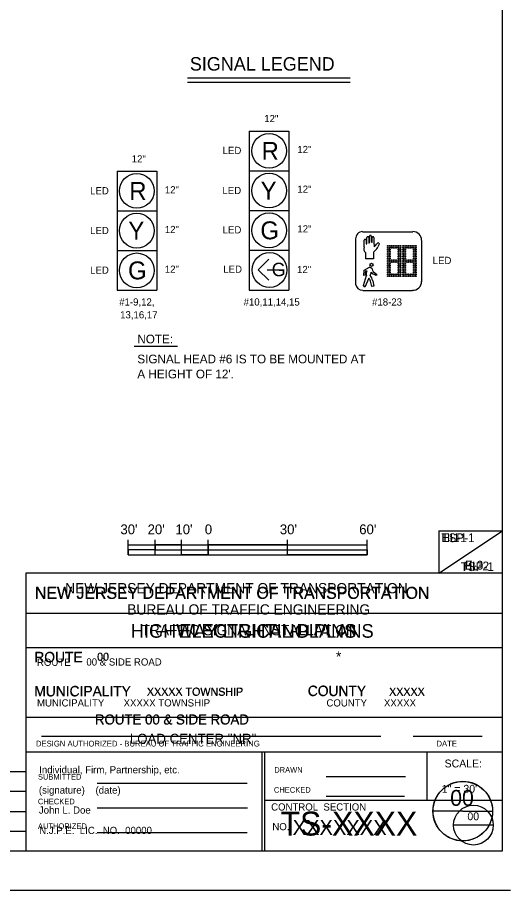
# Model space of a CAD drawing. Extents: x 488740 to 507913, y 466518 to 497949.
# Drawn here: x 507910.118 to 507910.636, y 496046.406 to 496047.323 of the extents above; entities that cross this region are included whole.
import ezdxf

# ---------------------------------------------------------------- set-up
doc = ezdxf.new("R2010")
doc.units = 0
for name, color, linetype in [('1', 7, 'Continuous'), ('11', 7, 'Continuous'), ('25', 7, 'Continuous'), ('26', 7, 'Continuous'), ('27', 7, 'Continuous'), ('31', 7, 'Continuous'), ('38', 7, 'Continuous'), ('9', 7, 'Continuous')]:
    doc.layers.add(name, color=color, linetype=linetype)

msp = doc.modelspace()

# ---------------------------------------------------------------- linework, layer by layer
at = {"layer": '1'}
for p, q in [((507910.6273, 496046.44783), (507910.6273, 496048.19783)), ((507910.6273, 496046.44783), (507910.6273, 496046.80647)), ((507910.23454, 496046.75859), (507910.23454, 496046.77434)), ((507910.26276, 496046.75859), (507910.26276, 496046.77434)), ((507910.29032, 496046.75859), (507910.29032, 496046.77434)), ((507910.31853, 496046.75859), (507910.31853, 496046.77434)), ((507910.40186, 496046.75859), (507910.40186, 496046.77434)), ((507910.4852, 496046.75859), (507910.4852, 496046.77434)), ((507910.23454, 496046.76909), (507910.4852, 496046.76909)), ((507910.23454, 496046.75859), (507910.4852, 496046.75859)), ((507907.8773, 496046.44783), (507910.6273, 496046.44783)), ((507910.63583, 496046.40617), (507907.72408, 496046.40617))]:
    msp.add_line(p, q, dxfattribs=at)
for points in [[(507910.23454, 496046.76351), (507910.2352, 496046.76384)], [(507910.26276, 496046.75859), (507910.26276, 496046.75859)]]:
    msp.add_lwpolyline(points, dxfattribs=at)
for points in [[(507910.23454, 496046.75859), (507910.26276, 496046.75859), (507910.26276, 496046.76384), (507910.23454, 496046.76384)], [(507910.26276, 496046.76384), (507910.29032, 496046.76384), (507910.29032, 496046.76909), (507910.26276, 496046.76909)], [(507910.29032, 496046.76384), (507910.31853, 496046.76384), (507910.31853, 496046.75859), (507910.29032, 496046.75859)], [(507910.31853, 496046.76384), (507910.40186, 496046.76384), (507910.40186, 496046.76909), (507910.31853, 496046.76909)], [(507910.40186, 496046.76384), (507910.4852, 496046.76384), (507910.4852, 496046.75859), (507910.40186, 496046.75859)]]:
    msp.add_lwpolyline(points, close=True, dxfattribs=at)
at = {"layer": '25'}
for p, q in [((507910.5607, 496046.7395), (507910.6273, 496046.78379)), ((507910.5607, 496046.78379), (507910.6273, 496046.78379)), ((507910.5607, 496046.78379), (507910.5607, 496046.7395)), ((507910.1273, 496046.44783), (507910.1273, 496046.7395)), ((507910.6273, 496046.7395), (507910.1273, 496046.7395)), ((507910.1273, 496046.69751), (507910.6273, 496046.69751)), ((507910.6273, 496046.55151), (507910.1273, 496046.55151)), ((507910.37467, 496046.55151), (507910.37467, 496046.44783)), ((507910.58563, 496046.4895), (507910.55479, 496046.4895)), ((507910.58563, 496046.4895), (507910.6168, 496046.4895))]:
    msp.add_line(p, q, dxfattribs=at)
msp.add_circle((507910.58579, 496046.48959), 0.03125, dxfattribs=at)
at = {"layer": '26'}
for p, q in [((507910.5607, 496046.78379), (507910.6273, 496046.78379)), ((507910.5607, 496046.78379), (507910.5607, 496046.7395)), ((507910.5607, 496046.7395), (507910.6273, 496046.78379)), ((507910.1273, 496046.44783), (507910.1273, 496046.7395)), ((507910.6273, 496046.7395), (507910.1273, 496046.7395)), ((507910.1273, 496046.69751), (507910.6273, 496046.69751)), ((507910.58563, 496046.4895), (507910.55479, 496046.4895)), ((507910.58563, 496046.4895), (507910.6168, 496046.4895))]:
    msp.add_line(p, q, dxfattribs=at)
msp.add_circle((507910.58564, 496046.48943), 0.03125, dxfattribs=at)
at = {"layer": '27'}
for p, q in [((507910.5607, 496046.78379), (507910.6273, 496046.78379)), ((507910.5607, 496046.78379), (507910.5607, 496046.7395)), ((507910.5607, 496046.7395), (507910.6273, 496046.78379)), ((507910.6271, 496046.73938), (507910.1271, 496046.73938)), ((507910.1273, 496046.44783), (507910.1273, 496046.7395)), ((507910.6271, 496046.66096), (507910.1271, 496046.66096)), ((507910.6271, 496046.5878), (507910.1271, 496046.5878)), ((507910.14337, 496046.56824), (507910.49967, 496046.56824)), ((507910.53346, 496046.56824), (507910.60597, 496046.56824)), ((507910.6271, 496046.55138), (507910.1271, 496046.55138)), ((507910.37795, 496046.44783), (507910.37795, 496046.55151)), ((507910.54823, 496046.50098), (507910.54823, 496046.55151)), ((507909.68861, 496046.53117), (507910.1273, 496046.53117)), ((507910.44247, 496046.52575), (507910.52559, 496046.52575)), ((507910.2021, 496046.51903), (507910.35925, 496046.51903)), ((507910.2021, 496046.51903), (507910.35925, 496046.51903)), ((507909.68861, 496046.5105), (507910.1273, 496046.5105)), ((507910.44247, 496046.50509), (507910.52461, 496046.50509)), ((507910.6271, 496046.50086), (507910.37776, 496046.50086)), ((507909.68861, 496046.48917), (507910.1273, 496046.48917)), ((507910.2021, 496046.49311), (507910.35958, 496046.49311)), ((507910.2021, 496046.49311), (507910.35958, 496046.49311)), ((507909.68861, 496046.4685), (507910.1273, 496046.4685)), ((507910.2021, 496046.46719), (507910.35925, 496046.46719)), ((507910.57601, 496046.47507), (507910.61778, 496046.47507))]:
    msp.add_line(p, q, dxfattribs=at)
msp.add_circle((507910.59687, 496046.47484), 0.02087, dxfattribs=at)
at = {"layer": '31'}
for p, q in [((507910.29682, 496047.25947), (507910.46751, 496047.25947)), ((507910.29689, 496047.25492), (507910.46751, 496047.25492)), ((507910.36155, 496047.20341), (507910.36155, 496047.07841)), ((507910.36155, 496047.20341), (507910.40322, 496047.20341)), ((507910.40322, 496047.20341), (507910.40322, 496047.12008)), ((507910.22277, 496047.16142), (507910.22277, 496047.03642)), ((507910.22277, 496047.16142), (507910.26444, 496047.16142)), ((507910.26444, 496047.16142), (507910.26444, 496047.07808)), ((507910.36155, 496047.16175), (507910.40322, 496047.16175)), ((507910.22277, 496047.11975), (507910.26444, 496047.11975)), ((507910.36155, 496047.12008), (507910.40322, 496047.12008)), ((507910.40322, 496047.12008), (507910.40322, 496047.12008)), ((507910.40322, 496047.12008), (507910.40322, 496047.07841)), ((507910.4731, 496047.09022), (507910.4731, 496047.04265)), ((507910.48031, 496047.09777), (507910.53314, 496047.09777)), ((507910.48503, 496047.08558), (507910.48503, 496047.09187)), ((507910.48694, 496047.09187), (507910.48694, 496047.08642)), ((507910.4878, 496047.08642), (507910.4878, 496047.09326)), ((507910.4897, 496047.09326), (507910.4897, 496047.08712)), ((507910.49056, 496047.08712), (507910.49056, 496047.09187)), ((507910.49247, 496047.09187), (507910.49247, 496047.08558)), ((507910.48227, 496047.08209), (507910.48227, 496047.08897)), ((507910.48418, 496047.08897), (507910.48418, 496047.08558)), ((507910.54232, 496047.08858), (507910.54232, 496047.04528)), ((507910.22277, 496047.07808), (507910.26444, 496047.07808)), ((507910.26444, 496047.07808), (507910.26444, 496047.07808)), ((507910.26444, 496047.07808), (507910.26444, 496047.03642)), ((507910.36155, 496047.07841), (507910.36155, 496047.03642)), ((507910.36155, 496047.07841), (507910.40322, 496047.07841)), ((507910.36155, 496047.07841), (507910.40322, 496047.07841)), ((507910.40322, 496047.07841), (507910.40322, 496047.03642)), ((507910.48377, 496047.06949), (507910.48377, 496047.07579)), ((507910.4919, 496047.07605), (507910.4919, 496047.06949)), ((507910.37106, 496047.05774), (507910.38222, 496047.0689)), ((507910.4919, 496047.06949), (507910.48377, 496047.06949)), ((507910.37106, 496047.05774), (507910.38222, 496047.04692)), ((507910.38025, 496047.05774), (507910.39567, 496047.05774)), ((507910.48197, 496047.05197), (507910.48222, 496047.05765)), ((507910.48222, 496047.05765), (507910.48772, 496047.06054)), ((507910.49486, 496047.05195), (507910.49119, 496047.05379)), ((507910.49168, 496047.05601), (507910.4956, 496047.05293)), ((507910.48161, 496047.04147), (507910.48457, 496047.05188)), ((507910.48313, 496047.05236), (507910.48197, 496047.05197)), ((507910.48693, 496047.04899), (507910.483, 496047.03981)), ((507910.49035, 496047.04033), (507910.48877, 496047.04611)), ((507910.49113, 496047.04637), (507910.49245, 496047.04086)), ((507910.4956, 496047.05293), (507910.49486, 496047.05195)), ((507910.22277, 496047.03642), (507910.26444, 496047.03642)), ((507910.36155, 496047.03642), (507910.40322, 496047.03642)), ((507910.48064, 496047.03609), (507910.53281, 496047.03609)), ((507910.483, 496047.03981), (507910.48161, 496047.04147)), ((507910.49245, 496047.04086), (507910.49035, 496047.04033)), ((507910.24081, 496046.97769), (507910.28642, 496046.97769))]:
    msp.add_line(p, q, dxfattribs=at)
for centre, radius in [((507910.38245, 496047.18279), 0.01826), ((507910.24355, 496047.14074), 0.01826), ((507910.38245, 496047.14105), 0.01826), ((507910.38245, 496047.09932), 0.01826), ((507910.24355, 496047.09901), 0.01826), ((507910.50717, 496047.08292), 0.000466), ((507910.50717, 496047.08106), 0.000466), ((507910.50903, 496047.08292), 0.000466), ((507910.50903, 496047.08106), 0.000466), ((507910.5109, 496047.08292), 0.000466), ((507910.5109, 496047.08106), 0.000466), ((507910.51276, 496047.08292), 0.000466), ((507910.51276, 496047.08106), 0.000466), ((507910.51463, 496047.08292), 0.000466), ((507910.51463, 496047.08106), 0.000466), ((507910.51649, 496047.08292), 0.000466), ((507910.51649, 496047.08106), 0.000466), ((507910.51836, 496047.08292), 0.000466), ((507910.51836, 496047.08106), 0.000466), ((507910.52022, 496047.08292), 0.000466), ((507910.52022, 496047.08106), 0.000466), ((507910.52322, 496047.08292), 0.000466), ((507910.52322, 496047.08106), 0.000466), ((507910.52508, 496047.08292), 0.000466), ((507910.52508, 496047.08106), 0.000466), ((507910.52695, 496047.08292), 0.000466), ((507910.52695, 496047.08106), 0.000466), ((507910.52881, 496047.08292), 0.000466), ((507910.52881, 496047.08106), 0.000466), ((507910.53067, 496047.08292), 0.000466), ((507910.53067, 496047.08106), 0.000466), ((507910.53254, 496047.08292), 0.000466), ((507910.53254, 496047.08106), 0.000466), ((507910.5344, 496047.08292), 0.000466), ((507910.5344, 496047.08106), 0.000466), ((507910.53627, 496047.08292), 0.000466), ((507910.53627, 496047.08106), 0.000466), ((507910.24355, 496047.05728), 0.01826), ((507910.38288, 496047.05768), 0.01826), ((507910.50717, 496047.07919), 0.000466), ((507910.50717, 496047.07733), 0.000466), ((507910.50717, 496047.07546), 0.000466), ((507910.50717, 496047.0736), 0.000466), ((507910.50717, 496047.07173), 0.000466), ((507910.50903, 496047.07919), 0.000466), ((507910.50903, 496047.07733), 0.000466), ((507910.50903, 496047.07546), 0.000466), ((507910.50903, 496047.0736), 0.000466), ((507910.50903, 496047.07173), 0.000466), ((507910.51836, 496047.07919), 0.000466), ((507910.51836, 496047.07733), 0.000466), ((507910.51836, 496047.07546), 0.000466), ((507910.51836, 496047.0736), 0.000466), ((507910.51836, 496047.07173), 0.000466), ((507910.52022, 496047.07919), 0.000466), ((507910.52022, 496047.07733), 0.000466), ((507910.52022, 496047.07546), 0.000466), ((507910.52022, 496047.0736), 0.000466), ((507910.52022, 496047.07173), 0.000466), ((507910.52322, 496047.07919), 0.000466), ((507910.52322, 496047.07733), 0.000466), ((507910.52322, 496047.07546), 0.000466), ((507910.52322, 496047.0736), 0.000466), ((507910.52322, 496047.07173), 0.000466), ((507910.52508, 496047.07919), 0.000466), ((507910.52508, 496047.07733), 0.000466), ((507910.52508, 496047.07546), 0.000466), ((507910.52508, 496047.0736), 0.000466), ((507910.52508, 496047.07173), 0.000466), ((507910.5344, 496047.07919), 0.000466), ((507910.5344, 496047.07733), 0.000466), ((507910.5344, 496047.07546), 0.000466), ((507910.5344, 496047.0736), 0.000466), ((507910.5344, 496047.07173), 0.000466), ((507910.53627, 496047.07919), 0.000466), ((507910.53627, 496047.07733), 0.000466), ((507910.53627, 496047.07546), 0.000466), ((507910.53627, 496047.0736), 0.000466), ((507910.53627, 496047.07173), 0.000466), ((507910.48989, 496047.0631), 0.00169), ((507910.50717, 496047.06987), 0.000466), ((507910.50717, 496047.06801), 0.000466), ((507910.50717, 496047.06614), 0.000466), ((507910.50717, 496047.06428), 0.000466), ((507910.50717, 496047.06241), 0.000466), ((507910.50903, 496047.06987), 0.000466), ((507910.50903, 496047.06801), 0.000466), ((507910.50903, 496047.06614), 0.000466), ((507910.50903, 496047.06428), 0.000466), ((507910.50903, 496047.06241), 0.000466), ((507910.5109, 496047.06801), 0.000466), ((507910.5109, 496047.06614), 0.000466), ((507910.51276, 496047.06801), 0.000466), ((507910.51276, 496047.06614), 0.000466), ((507910.51463, 496047.06801), 0.000466), ((507910.51463, 496047.06614), 0.000466), ((507910.51649, 496047.06801), 0.000466), ((507910.51649, 496047.06614), 0.000466), ((507910.51836, 496047.06987), 0.000466), ((507910.51836, 496047.06801), 0.000466), ((507910.51836, 496047.06614), 0.000466), ((507910.51836, 496047.06428), 0.000466), ((507910.51836, 496047.06241), 0.000466), ((507910.52022, 496047.06987), 0.000466), ((507910.52022, 496047.06801), 0.000466), ((507910.52022, 496047.06614), 0.000466), ((507910.52022, 496047.06428), 0.000466), ((507910.52022, 496047.06241), 0.000466), ((507910.52322, 496047.06987), 0.000466), ((507910.52322, 496047.068), 0.000466), ((507910.52322, 496047.06614), 0.000466), ((507910.52322, 496047.06428), 0.000466), ((507910.52322, 496047.06241), 0.000466), ((507910.52508, 496047.06987), 0.000466), ((507910.52508, 496047.068), 0.000466), ((507910.52508, 496047.06614), 0.000466), ((507910.52508, 496047.06428), 0.000466), ((507910.52508, 496047.06241), 0.000466), ((507910.52695, 496047.068), 0.000466), ((507910.52695, 496047.06614), 0.000466), ((507910.52881, 496047.068), 0.000466), ((507910.52881, 496047.06614), 0.000466), ((507910.53067, 496047.068), 0.000466), ((507910.53067, 496047.06614), 0.000466), ((507910.53254, 496047.068), 0.000466), ((507910.53254, 496047.06614), 0.000466), ((507910.5344, 496047.06987), 0.000466), ((507910.5344, 496047.068), 0.000466), ((507910.5344, 496047.06614), 0.000466), ((507910.5344, 496047.06428), 0.000466), ((507910.5344, 496047.06241), 0.000466), ((507910.53627, 496047.06987), 0.000466), ((507910.53627, 496047.068), 0.000466), ((507910.53627, 496047.06614), 0.000466), ((507910.53627, 496047.06428), 0.000466), ((507910.53627, 496047.06241), 0.000466), ((507910.50717, 496047.06055), 0.000466), ((507910.50717, 496047.05868), 0.000466), ((507910.50717, 496047.05682), 0.000466), ((507910.50717, 496047.05495), 0.000466), ((507910.50717, 496047.05309), 0.000466), ((507910.50903, 496047.06055), 0.000466), ((507910.50903, 496047.05868), 0.000466), ((507910.50903, 496047.05682), 0.000466), ((507910.50903, 496047.05495), 0.000466), ((507910.50903, 496047.05309), 0.000466), ((507910.5109, 496047.05309), 0.000466), ((507910.51276, 496047.05309), 0.000466), ((507910.51463, 496047.05309), 0.000466), ((507910.51649, 496047.05309), 0.000466), ((507910.51836, 496047.06055), 0.000466), ((507910.51836, 496047.05868), 0.000466), ((507910.51836, 496047.05682), 0.000466), ((507910.51836, 496047.05495), 0.000466), ((507910.51836, 496047.05309), 0.000466), ((507910.52022, 496047.06055), 0.000466), ((507910.52022, 496047.05868), 0.000466), ((507910.52022, 496047.05682), 0.000466), ((507910.52022, 496047.05495), 0.000466), ((507910.52022, 496047.05309), 0.000466), ((507910.52322, 496047.06055), 0.000466), ((507910.52322, 496047.05868), 0.000466), ((507910.52322, 496047.05682), 0.000466), ((507910.52322, 496047.05495), 0.000466), ((507910.52322, 496047.05309), 0.000466), ((507910.52508, 496047.06055), 0.000466), ((507910.52508, 496047.05868), 0.000466), ((507910.52508, 496047.05682), 0.000466), ((507910.52508, 496047.05495), 0.000466), ((507910.52508, 496047.05309), 0.000466), ((507910.52695, 496047.05309), 0.000466), ((507910.52881, 496047.05309), 0.000466), ((507910.53067, 496047.05309), 0.000466), ((507910.53254, 496047.05309), 0.000466), ((507910.5344, 496047.06055), 0.000466), ((507910.5344, 496047.05868), 0.000466), ((507910.5344, 496047.05682), 0.000466), ((507910.5344, 496047.05495), 0.000466), ((507910.5344, 496047.05309), 0.000466), ((507910.53627, 496047.06055), 0.000466), ((507910.53627, 496047.05868), 0.000466), ((507910.53627, 496047.05682), 0.000466), ((507910.53627, 496047.05495), 0.000466), ((507910.53627, 496047.05309), 0.000466), ((507910.50717, 496047.05123), 0.000466), ((507910.50903, 496047.05123), 0.000466), ((507910.5109, 496047.05123), 0.000466), ((507910.51276, 496047.05123), 0.000466), ((507910.51463, 496047.05123), 0.000466), ((507910.51649, 496047.05123), 0.000466), ((507910.51836, 496047.05123), 0.000466), ((507910.52022, 496047.05123), 0.000466), ((507910.52322, 496047.05123), 0.000466), ((507910.52508, 496047.05123), 0.000466), ((507910.52695, 496047.05123), 0.000466), ((507910.52881, 496047.05123), 0.000466), ((507910.53067, 496047.05123), 0.000466), ((507910.53254, 496047.05123), 0.000466), ((507910.5344, 496047.05123), 0.000466), ((507910.53627, 496047.05123), 0.000466)]:
    msp.add_circle(centre, radius, dxfattribs=at)
for centre, radius, start, end in [((507910.48062, 496047.09065), 0.00738, 91.27292, 181.27314), ((507910.48599, 496047.09169), 0.000972, 10.90231, 169.09769), ((507910.48875, 496047.09308), 0.000972, 10.90231, 169.09769), ((507910.49152, 496047.09169), 0.000972, 10.90231, 169.09769), ((507910.53328, 496047.08884), 0.00919, 0.00182, 89.99818), ((507910.48693, 496047.07987), 0.00516, 154.50261, 232.25136), ((507910.48323, 496047.08879), 0.000972, 10.90231, 169.09769), ((507910.4846, 496047.08559), 0.000428, 181.8307, 358.1693), ((507910.48737, 496047.08643), 0.000428, 181.8307, 358.1693), ((507910.49013, 496047.08714), 0.000428, 181.8307, 358.1693), ((507910.51543, 496047.08614), 0.02297, 181.44031, 190.00181), ((507910.48078, 496047.09526), 0.01779, 312.54891, 326.97837), ((507910.48661, 496047.08631), 0.01087, 311.8242, 337.12784), ((507910.49688, 496047.08459), 0.00153, 39.26984, 140.73016), ((507910.50617, 496047.07878), 0.0101, 143.68967, 160.88423), ((507910.49762, 496047.08517), 0.000586, 314.97386, 41.06788), ((507910.4971, 496047.07331), 0.00588, 123.46897, 152.18721), ((507910.51145, 496047.05078), 0.02837, 167.57904, 176.81016), ((507910.48457, 496047.0602), 0.00342, 256.06823, 277.46346), ((507910.49195, 496047.0537), 0.0076, 155.85972, 193.89568), ((507910.48699, 496047.05591), 0.00469, 1.20507, 81.00882), ((507910.47258, 496047.05865), 0.01731, 336.98748, 349.30722), ((507910.49266, 496047.05683), 0.00337, 204.34516, 244.12888), ((507910.48344, 496047.04474), 0.0055, 14.35946, 50.58292), ((507910.47972, 496047.04431), 0.0116, 10.20822, 40.71846), ((507910.53334, 496047.04547), 0.00912, 267.53748, 0.45235), ((507910.48041, 496047.04355), 0.00721, 185.04835, 272.93348)]:
    msp.add_arc(centre, radius, start, end, dxfattribs=at)

# ---------------------------------------------------------------- texts
at = {"layer": '1'}
for s, height, p in [("30'", 0.010317, (507910.22634, 496046.78024)), ("20'", 0.010317, (507910.25488, 496046.78024)), ("10'", 0.010317, (507910.28408, 496046.78024)), ('0', 0.01032, (507910.31492, 496046.78024)), ("30'", 0.010317, (507910.39366, 496046.78024)), ("60'", 0.010317, (507910.477, 496046.78024))]:
    msp.add_text(s, height=height, dxfattribs=at).set_placement(p)
at = {"layer": '11'}
for s, height, p in [('HL-1', 0.009167, (507910.56332, 496046.77198)), ('HL-2', 0.009167, (507910.58672, 496046.74237)), ('HIGHWAY LIGHTING PLANS', 0.0142992, (507910.2372, 496046.67159))]:
    msp.add_text(s, height=height, dxfattribs=at).set_placement(p)
at = {"layer": '25'}
for s, height, p in [('NEW JERSEY DEPARTMENT OF TRANSPORTATION', 0.0124665, (507910.13681, 496046.7126)), ('ROUTE', 0.010827, (507910.13615, 496046.646)), ('00                      ', 0.0082992, (507910.2021, 496046.64764)), ('*', 0.01083, (507910.45257, 496046.64633)), ('MUNICIPALITY', 0.0108268, (507910.13615, 496046.61024)), ('XXXXX TOWNSHIP    ', 0.0083996, (507910.25427, 496046.61089)), ('COUNTY', 0.010827, (507910.42323, 496046.61056)), ('XXXXX        ', 0.0083996, (507910.50853, 496046.61089)), ('             ROUTE 00 & SIDE ROAD            ', 0.0103996, (507910.14958, 496046.58071)), ('CONTROL  SECTION', 0.0075453, (507910.38451, 496046.49016)), ('NO.', 0.007545, (507910.38583, 496046.46949)), ('XXXXXXX  ', 0.015797, (507910.40712, 496046.46457))]:
    msp.add_text(s, height=height, dxfattribs=at).set_placement(p)
at = {"layer": '26'}
for s, height, p in [('NEW JERSEY DEPARTMENT OF TRANSPORTATION', 0.0124665, (507910.13648, 496046.71227)), ('ROUTE', 0.010827, (507910.13583, 496046.64567)), ('00                      ', 0.0082992, (507910.20177, 496046.64731)), ('*', 0.01083, (507910.45258, 496046.64633)), ('MUNICIPALITY', 0.0108268, (507910.13583, 496046.60991)), ('XXXXX TOWNSHIP    ', 0.0083996, (507910.25394, 496046.61056)), ('COUNTY', 0.010827, (507910.4229, 496046.61024)), ('XXXXX        ', 0.0083996, (507910.5082, 496046.61056)), ('             ROUTE 00 & SIDE ROAD            ', 0.0103996, (507910.14928, 496046.58038)), ('               LOAD CENTER "NR"              ', 0.0103996, (507910.17827, 496046.56037)), ('Individual, Firm, Partnership, etc.', 0.0075453, (507910.14108, 496046.5292)), ('(signature)    (date)', 0.0075453, (507910.14075, 496046.50787)), ('00', 0.016665, (507910.57251, 496046.49508)), ('John L. Doe', 0.0075453, (507910.14075, 496046.48688)), ('N.J.P.E.  LIC.  NO.  00000', 0.0075453, (507910.14108, 496046.46555))]:
    msp.add_text(s, height=height, dxfattribs=at).set_placement(p)
at = {"layer": '27'}
for s, height, p in [('NEW JERSEY DEPARTMENT OF TRANSPORTATION', 0.0108268, (507910.16831, 496046.71818)), ('BUREAU OF TRAFFIC ENGINEERING', 0.0108268, (507910.23349, 496046.69587)), ('TRAFFIC SIGNAL INSTALLATION', 0.0108268, (507910.24836, 496046.67421)), ('00 & SIDE ROAD                                          ', 0.0075453, (507910.19062, 496046.64239)), ('ROUTE', 0.007545, (507910.13878, 496046.64206)), ('MUNICIPALITY', 0.0075453, (507910.13878, 496046.59941)), ('XXXXX TOWNSHIP             ', 0.0075453, (507910.22966, 496046.59941)), ('COUNTY', 0.007545, (507910.44259, 496046.59941)), ('XXXXX          ', 0.0075453, (507910.50295, 496046.59941)), ('DESIGN AUTHORIZED - BUREAU OF TRAFFIC ENGINEERING             ', 0.0060354, (507910.13762, 496046.55741)), ('DATE', 0.006035, (507910.55807, 496046.55741)), ('SCALE:', 0.008268, (507910.5666, 496046.53543)), ('DRAWN', 0.005906, (507910.3878, 496046.52986)), ('SUBMITTED                           ', 0.0059055, (507910.13976, 496046.52264)), ('CHECKED', 0.005906, (507910.38747, 496046.50886)), ('1" = 30\'', 0.008268, (507910.56365, 496046.50886)), ('CHECKED                            ', 0.0059055, (507910.13976, 496046.49672)), ('TS-XXXX', 0.025098, (507910.39436, 496046.46391)), ('00', 0.008268, (507910.59055, 496046.47999)), ('AUTHORIZED                          ', 0.0059055, (507910.13976, 496046.4708))]:
    msp.add_text(s, height=height, dxfattribs=at).set_placement(p)
at = {"layer": '31'}
for s, height, p in [('SIGNAL LEGEND', 0.0141083, (507910.29921, 496047.26706)), ('12"', 0.007545, (507910.3773, 496047.21293)), ('R', 0.01881, (507910.37449, 496047.17338)), ('LED', 0.007545, (507910.33366, 496047.17946)), ('12"', 0.007545, (507910.41207, 496047.18045)), ('12"', 0.007545, (507910.23819, 496047.1706)), ('R', 0.01881, (507910.23559, 496047.13134)), ('12"', 0.007545, (507910.27297, 496047.13812)), ('LED', 0.007545, (507910.33345, 496047.13745)), ('Y', 0.01881, (507910.37351, 496047.13165)), ('12"', 0.007545, (507910.41207, 496047.13878)), ('LED', 0.007545, (507910.19455, 496047.13714)), ('Y', 0.01881, (507910.23461, 496047.08961)), ('G', 0.01881, (507910.37323, 496047.08992)), ('LED', 0.007545, (507910.19455, 496047.09541)), ('12"', 0.007545, (507910.27297, 496047.09646)), ('LED', 0.007545, (507910.33366, 496047.09613)), ('12"', 0.007545, (507910.41207, 496047.09711)), ('G', 0.01881, (507910.23433, 496047.04788)), ('G', 0.01411, (507910.38517, 496047.05118)), ('LED', 0.007545, (507910.55413, 496047.06398)), ('LED', 0.007545, (507910.19455, 496047.05381)), ('12"', 0.007545, (507910.27297, 496047.05479)), ('LED', 0.007545, (507910.33432, 496047.05479)), ('12"', 0.007545, (507910.41175, 496047.05446)), ('#1-9,12,', 0.007545, (507910.22507, 496047.02034)), ('#10,11,14,15', 0.0075453, (507910.35564, 496047.02034)), ('#18-23', 0.007545, (507910.49049, 496047.02034)), ('13,16,17', 0.007545, (507910.22605, 496047.00689)), ('NOTE:', 0.009187, (507910.24409, 496046.98064)), ('SIGNAL HEAD #6 IS TO BE MOUNTED AT', 0.009187, (507910.24409, 496046.95965)), ("A HEIGHT OF 12'.", 0.009187, (507910.24409, 496046.9439))]:
    msp.add_text(s, height=height, dxfattribs=at).set_placement(p)
at = {"layer": '38'}
for p in [(507910.56332, 496046.77198), (507910.58363, 496046.74159)]:
    msp.add_text('TSP-1', height=0.009167, dxfattribs=at).set_placement(p)
at = {"layer": '9'}
for s, height, p in [('E-1', 0.009167, (507910.56332, 496046.77198)), ('E-1', 0.009167, (507910.56332, 496046.77198)), ('E-3', 0.009167, (507910.58809, 496046.7432)), ('ELECTRICAL PLANS', 0.0142992, (507910.28806, 496046.67159))]:
    msp.add_text(s, height=height, dxfattribs=at).set_placement(p)

doc.saveas('drawing.dxf')
